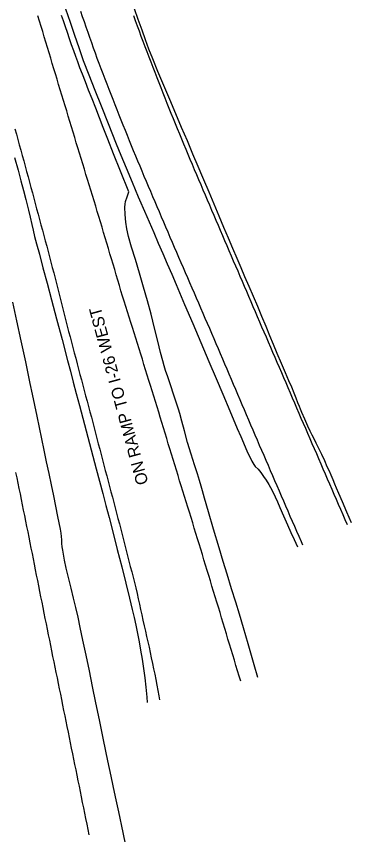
# Model space of a CAD drawing. Extents: x 1948091 to 1975253, y 787267 to 823306.
# Drawn here: x 1966562.1 to 1966713.8, y 789832.7 to 790203 of the extents above; entities that cross this region are included whole.
import ezdxf

# ---------------------------------------------------------------- set-up
doc = ezdxf.new("R2010")
doc.units = 0
for name, color, linetype in [('RD_EX_Pavement_Markings', 7, 'Continuous'), ('RD_EX_Road', 7, 'Continuous'), ('RD_TX_RoadID', 7, 'Continuous')]:
    doc.layers.add(name, color=color, linetype=linetype)

msp = doc.modelspace()

# ---------------------------------------------------------------- linework, layer by layer
at = {"layer": 'RD_EX_Pavement_Markings'}
for points in [[(1966591.11, 790205.32), (1966591.91, 790202.95), (1966592.71, 790200.59), (1966593.53, 790198.23), (1966594.37, 790195.87), (1966595.2, 790193.51), (1966596.03, 790191.16), (1966596.87, 790188.8), (1966597.7, 790186.45), (1966598.57, 790184.1), (1966599.45, 790181.76), (1966600.33, 790179.43), (1966601.21, 790177.09), (1966602.09, 790174.75), (1966602.97, 790172.41), (1966603.88, 790170.08), (1966604.8, 790167.76), (1966605.72, 790165.44), (1966606.64, 790163.11), (1966607.56, 790160.79), (1966608.48, 790158.47), (1966609.4, 790156.14), (1966610.34, 790153.83), (1966611.27, 790151.51), (1966612.21, 790149.2), (1966613.15, 790146.88), (1966614.08, 790144.56), (1966615.02, 790142.25), (1966615.97, 790139.94), (1966616.93, 790137.63), (1966617.9, 790135.33), (1966618.86, 790133.02), (1966619.82, 790130.71), (1966620.79, 790128.41), (1966621.75, 790126.1), (1966622.73, 790123.8), (1966623.71, 790121.51), (1966624.7, 790119.21), (1966625.68, 790116.91), (1966626.66, 790114.62), (1966627.65, 790112.32), (1966628.63, 790110.02), (1966629.62, 790107.73), (1966630.6, 790105.43), (1966631.59, 790103.13), (1966632.58, 790100.84), (1966633.56, 790098.54), (1966634.55, 790096.24), (1966635.54, 790093.95), (1966636.52, 790091.65), (1966637.52, 790089.36), (1966638.51, 790087.07), (1966639.51, 790084.78), (1966640.51, 790082.48), (1966641.5, 790080.19), (1966642.5, 790077.9), (1966643.5, 790075.61), (1966644.49, 790073.32), (1966645.48, 790071.02), (1966646.47, 790068.72), (1966647.46, 790066.43), (1966648.45, 790064.13), (1966649.44, 790061.84), (1966650.43, 790059.54), (1966651.42, 790057.25), (1966652.41, 790054.95), (1966653.39, 790052.65), (1966654.37, 790050.35), (1966655.35, 790048.06), (1966656.34, 790045.76), (1966657.32, 790043.46), (1966658.3, 790041.16), (1966659.28, 790038.86), (1966660.27, 790036.56), (1966661.24, 790034.26), (1966662.22, 790031.96), (1966663.2, 790029.66), (1966664.18, 790027.36), (1966665.15, 790025.06), (1966666.13, 790022.76), (1966667.11, 790020.46), (1966668.09, 790018.16), (1966669.08, 790015.86), (1966670.07, 790013.57), (1966671.07, 790011.28), (1966672.06, 790008.98), (1966673.06, 790006.69), (1966674.05, 790004.4), (1966675.05, 790002.1), (1966676.04, 789999.81), (1966677.04, 789997.52), (1966678.02, 789995.22), (1966679, 789992.92), (1966679.99, 789990.62), (1966680.97, 789988.32), (1966681.95, 789986.02), (1966682.94, 789983.73), (1966683.92, 789981.43), (1966684.9, 789979.13), (1966685.91, 789976.84), (1966686.91, 789974.55), (1966687.92, 789972.26), (1966688.92, 789969.97), (1966689.93, 789967.68), (1966690.93, 789965.39), (1966691.6, 789963.88)], [(1966663.63, 789902.06), (1966662.91, 789904.45), (1966662.19, 789906.84), (1966661.47, 789909.23), (1966660.75, 789911.63), (1966660.03, 789914.02), (1966659.31, 789916.41), (1966658.58, 789918.8), (1966657.86, 789921.19), (1966657.14, 789923.58), (1966656.42, 789925.97), (1966655.7, 789928.36), (1966654.98, 789930.75), (1966654.26, 789933.15), (1966653.54, 789935.54), (1966652.81, 789937.93), (1966652.09, 789940.32), (1966651.36, 789942.7), (1966650.63, 789945.09), (1966649.91, 789947.48), (1966649.18, 789949.87), (1966648.45, 789952.26), (1966647.73, 789954.65), (1966647, 789957.04), (1966646.27, 789959.43), (1966645.54, 789961.82), (1966644.82, 789964.21), (1966644.09, 789966.6), (1966643.36, 789968.99), (1966642.63, 789971.37), (1966641.89, 789973.76), (1966641.15, 789976.15), (1966640.42, 789978.53), (1966639.68, 789980.92), (1966638.94, 789983.31), (1966638.21, 789985.69), (1966637.47, 789988.08), (1966636.73, 789990.47), (1966635.99, 789992.85), (1966635.26, 789995.24), (1966634.52, 789997.63), (1966633.78, 790000.02), (1966633.05, 790002.4), (1966632.32, 790004.8), (1966631.6, 790007.19), (1966630.87, 790009.58), (1966630.15, 790011.97), (1966629.42, 790014.36), (1966628.69, 790016.75), (1966627.97, 790019.14), (1966627.24, 790021.53), (1966626.51, 790023.92), (1966625.77, 790026.31), (1966625.03, 790028.7), (1966624.29, 790031.08), (1966623.55, 790033.47), (1966622.81, 790035.85), (1966622.07, 790038.24), (1966621.33, 790040.63), (1966620.59, 790043.01), (1966619.85, 790045.4), (1966619.11, 790047.79), (1966618.36, 790050.17), (1966617.62, 790052.56), (1966616.87, 790054.94), (1966616.13, 790057.33), (1966615.38, 790059.72), (1966614.63, 790062.1), (1966613.89, 790064.48), (1966613.14, 790066.87), (1966612.4, 790069.26), (1966611.65, 790071.64), (1966610.9, 790074.03), (1966610.16, 790076.41), (1966609.42, 790078.8), (1966608.72, 790081.2), (1966608.02, 790083.6), (1966607.31, 790086), (1966606.61, 790088.4), (1966605.89, 790090.79), (1966605.17, 790093.19), (1966604.45, 790095.58), (1966603.74, 790097.98), (1966603.02, 790100.37), (1966602.3, 790102.77), (1966601.58, 790105.16), (1966600.86, 790107.55), (1966600.14, 790109.95), (1966599.43, 790112.34), (1966598.71, 790114.74), (1966597.99, 790117.13), (1966597.26, 790119.52), (1966596.53, 790121.91), (1966595.8, 790124.3), (1966595.07, 790126.7), (1966594.34, 790129.09), (1966593.6, 790131.48), (1966592.87, 790133.87), (1966592.14, 790136.26), (1966591.41, 790138.65), (1966590.68, 790141.04), (1966589.95, 790143.43), (1966589.22, 790145.82), (1966588.5, 790148.22), (1966587.77, 790150.61), (1966587.04, 790153), (1966586.31, 790155.39), (1966585.58, 790157.78), (1966584.86, 790160.17), (1966584.13, 790162.56), (1966583.4, 790164.96), (1966582.67, 790167.35), (1966581.94, 790169.74), (1966581.21, 790172.13), (1966580.49, 790174.52), (1966579.77, 790176.92), (1966579.05, 790179.31), (1966578.33, 790181.71), (1966577.61, 790184.1), (1966576.88, 790186.49), (1966576.16, 790188.89), (1966575.44, 790191.28), (1966574.72, 790193.67), (1966574, 790196.07), (1966573.28, 790198.46), (1966572.56, 790200.85), (1966571.84, 790203.25)], [(1966711.93, 789972.85), (1966710.93, 789975.15), (1966709.94, 789977.44), (1966708.94, 789979.74), (1966707.95, 789982.03), (1966706.96, 789984.32), (1966705.96, 789986.62), (1966704.97, 789988.91), (1966703.97, 789991.2), (1966702.98, 789993.5), (1966701.99, 789995.79), (1966701, 789998.09), (1966700.01, 790000.38), (1966699.02, 790002.68), (1966698.03, 790004.98), (1966697.04, 790007.27), (1966696.05, 790009.57), (1966695.05, 790011.86), (1966694.05, 790014.15), (1966693.06, 790016.44), (1966692.06, 790018.74), (1966691.07, 790021.03), (1966690.07, 790023.32), (1966689.07, 790025.62), (1966688.08, 790027.91), (1966687.1, 790030.21), (1966686.11, 790032.51), (1966685.13, 790034.81), (1966684.15, 790037.1), (1966683.16, 790039.4), (1966682.18, 790041.7), (1966681.19, 790044), (1966680.21, 790046.3), (1966679.21, 790048.59), (1966678.22, 790050.88), (1966677.23, 790053.18), (1966676.24, 790055.47), (1966675.25, 790057.77), (1966674.26, 790060.06), (1966673.26, 790062.36), (1966672.28, 790064.65), (1966671.29, 790066.95), (1966670.3, 790069.25), (1966669.31, 790071.54), (1966668.33, 790073.84), (1966667.34, 790076.14), (1966666.35, 790078.44), (1966665.37, 790080.73), (1966664.38, 790083.03), (1966663.4, 790085.33), (1966662.41, 790087.62), (1966661.42, 790089.92), (1966660.44, 790092.22), (1966659.45, 790094.51), (1966658.47, 790096.81), (1966657.48, 790099.11), (1966656.49, 790101.4), (1966655.51, 790103.7), (1966654.52, 790106), (1966653.54, 790108.29), (1966652.55, 790110.59), (1966651.56, 790112.89), (1966650.58, 790115.18), (1966649.59, 790117.48), (1966648.6, 790119.78), (1966647.62, 790122.07), (1966646.64, 790124.37), (1966645.67, 790126.68), (1966644.7, 790128.98), (1966643.73, 790131.28), (1966642.76, 790133.59), (1966641.79, 790135.89), (1966640.82, 790138.19), (1966639.85, 790140.5), (1966638.88, 790142.8), (1966637.93, 790145.11), (1966636.97, 790147.42), (1966636.02, 790149.73), (1966635.06, 790152.04), (1966634.1, 790154.35), (1966633.15, 790156.65), (1966632.19, 790158.96), (1966631.23, 790161.27), (1966630.31, 790163.59), (1966629.4, 790165.92), (1966628.49, 790168.25), (1966627.58, 790170.57), (1966626.67, 790172.9), (1966625.76, 790175.23), (1966624.85, 790177.56), (1966623.95, 790179.89), (1966623.06, 790182.23), (1966622.18, 790184.56), (1966621.29, 790186.9), (1966620.4, 790189.23), (1966619.51, 790191.57), (1966618.63, 790193.9), (1966617.77, 790196.25), (1966616.92, 790198.6), (1966616.07, 790200.95), (1966615.23, 790203.3)], [(1966561.43, 790152.13), (1966562.1, 790149.72), (1966562.76, 790147.31), (1966563.42, 790144.9), (1966564.09, 790142.49), (1966564.74, 790140.07), (1966565.39, 790137.66), (1966566.05, 790135.25), (1966566.7, 790132.84), (1966567.35, 790130.42), (1966568.01, 790128.01), (1966568.66, 790125.6), (1966569.31, 790123.18), (1966569.97, 790120.77), (1966570.62, 790118.36), (1966571.27, 790115.94), (1966571.92, 790113.53), (1966572.57, 790111.12), (1966573.22, 790108.7), (1966573.86, 790106.29), (1966574.51, 790103.87), (1966575.16, 790101.46), (1966575.8, 790099.04), (1966576.43, 790096.62), (1966577.07, 790094.21), (1966577.71, 790091.79), (1966578.35, 790089.37), (1966578.98, 790086.95), (1966579.62, 790084.54), (1966580.25, 790082.12), (1966580.86, 790079.69), (1966581.46, 790077.27), (1966582.07, 790074.84), (1966582.68, 790072.42), (1966583.29, 790069.99), (1966583.89, 790067.57), (1966584.5, 790065.14), (1966585.12, 790062.72), (1966585.75, 790060.3), (1966586.39, 790057.89), (1966587.03, 790055.47), (1966587.67, 790053.05), (1966588.3, 790050.64), (1966588.94, 790048.22), (1966589.58, 790045.8), (1966590.21, 790043.39), (1966590.86, 790040.97), (1966591.5, 790038.56), (1966592.15, 790036.14), (1966592.79, 790033.73), (1966593.44, 790031.31), (1966594.08, 790028.9), (1966594.73, 790026.48), (1966595.37, 790024.07), (1966596.02, 790021.66), (1966596.65, 790019.24), (1966597.28, 790016.82), (1966597.91, 790014.4), (1966598.54, 790011.98), (1966599.17, 790009.57), (1966599.8, 790007.15), (1966600.43, 790004.73), (1966601.06, 790002.31), (1966601.7, 789999.89), (1966602.33, 789997.48), (1966602.97, 789995.06), (1966603.61, 789992.65), (1966604.25, 789990.23), (1966604.89, 789987.81), (1966605.53, 789985.4), (1966606.16, 789982.98), (1966606.8, 789980.57), (1966607.44, 789978.15), (1966608.08, 789975.74), (1966608.7, 789973.32), (1966609.32, 789970.9), (1966609.94, 789968.48), (1966610.56, 789966.06), (1966611.18, 789963.64), (1966611.8, 789961.22), (1966612.42, 789958.8), (1966613.04, 789956.38), (1966613.66, 789953.96), (1966614.28, 789951.54), (1966614.91, 789949.13), (1966615.53, 789946.71), (1966616.16, 789944.29), (1966616.72, 789941.86), (1966617.28, 789939.43), (1966617.81, 789936.99), (1966618.34, 789934.55), (1966618.87, 789932.11), (1966619.4, 789929.67), (1966619.95, 789927.23), (1966620.49, 789924.79), (1966621.03, 789922.36), (1966621.58, 789919.92), (1966622.12, 789917.48), (1966622.64, 789915.04), (1966623.17, 789912.6), (1966623.7, 789910.16), (1966624.22, 789907.72), (1966624.75, 789905.28), (1966625.2, 789902.82), (1966625.65, 789900.37), (1966626.1, 789897.91), (1966626.53, 789895.45), (1966626.84, 789893.7)], [(1966561.76, 789996.62), (1966562.25, 789994.17), (1966562.75, 789991.73), (1966563.24, 789989.28), (1966563.74, 789986.83), (1966564.23, 789984.38), (1966564.73, 789981.93), (1966565.22, 789979.48), (1966565.72, 789977.03), (1966566.21, 789974.58), (1966566.7, 789972.14), (1966567.2, 789969.69), (1966567.69, 789967.24), (1966568.19, 789964.79), (1966568.68, 789962.34), (1966569.17, 789959.89), (1966569.66, 789957.44), (1966570.15, 789954.99), (1966570.63, 789952.54), (1966571.12, 789950.09), (1966571.61, 789947.64), (1966572.1, 789945.19), (1966572.59, 789942.74), (1966573.08, 789940.29), (1966573.57, 789937.84), (1966574.06, 789935.39), (1966574.55, 789932.94), (1966575.04, 789930.49), (1966575.53, 789928.04), (1966576.02, 789925.59), (1966576.52, 789923.14), (1966577.02, 789920.7), (1966577.51, 789918.25), (1966578.01, 789915.8), (1966578.51, 789913.35), (1966579, 789910.9), (1966579.5, 789908.45), (1966580, 789906.01), (1966580.49, 789903.56), (1966580.99, 789901.11), (1966581.49, 789898.66), (1966581.99, 789896.21), (1966582.48, 789893.77), (1966582.98, 789891.32), (1966583.48, 789888.87), (1966583.97, 789886.42), (1966584.47, 789883.97), (1966584.97, 789881.53), (1966585.47, 789879.08), (1966585.96, 789876.63), (1966586.46, 789874.18), (1966586.96, 789871.73), (1966587.45, 789869.29), (1966587.95, 789866.84), (1966588.45, 789864.39), (1966588.94, 789861.94), (1966589.44, 789859.5), (1966589.94, 789857.05), (1966590.44, 789854.6), (1966590.93, 789852.15), (1966591.43, 789849.7), (1966591.93, 789847.26), (1966592.42, 789844.81), (1966592.92, 789842.36), (1966593.42, 789839.91), (1966593.92, 789837.46), (1966594.43, 789835.02), (1966594.94, 789832.58)]]:
    msp.add_lwpolyline(points, dxfattribs=at)
at = {"layer": 'RD_EX_Road'}
for points in [[(1966584.38, 790206.41), (1966586.41, 790200.38), (1966588.43, 790194.43), (1966590.33, 790188.83), (1966592.39, 790183.06), (1966594.85, 790176.59), (1966597.58, 790169.64), (1966600.41, 790162.43), (1966603.57, 790154.48), (1966607.25, 790145.3), (1966609.36, 790140.13), (1966611.73, 790134.41), (1966614.43, 790127.98), (1966617.26, 790121.34), (1966617.87, 790119.92), (1966620.03, 790114.88), (1966622.16, 790109.95), (1966624.24, 790105.14), (1966626.3, 790100.39), (1966628.35, 790095.66), (1966630.39, 790090.94), (1966632.42, 790086.24), (1966634.41, 790081.59), (1966638.26, 790072.6), (1966641.92, 790063.96), (1966645.58, 790055.34), (1966649.23, 790046.79), (1966652.51, 790039.05), (1966655.47, 790032.03), (1966658.67, 790024.49), (1966662.09, 790016.46), (1966663.66, 790012.78), (1966666.43, 790006.31), (1966668.64, 790001.62), (1966669.51, 790000.17), (1966670.22, 789999.31), (1966671.49, 789998.05), (1966672.77, 789996.49), (1966674, 789994.8), (1966675.16, 789993.15), (1966676.38, 789991.14), (1966677.82, 789988.39), (1966679.2, 789985.57), (1966680.25, 789983.32), (1966681.39, 789980.76), (1966683.01, 789976.99), (1966684.77, 789972.92), (1966686.3, 789969.46), (1966687.76, 789966.23), (1966689.3, 789962.87)], [(1966646.47, 790130.1), (1966644.37, 790135.02), (1966642.01, 790140.6), (1966639.48, 790146.58), (1966636.89, 790152.68), (1966634.24, 790158.92), (1966631.54, 790165.29), (1966628.85, 790171.68), (1966626.19, 790178.01), (1966623.86, 790183.7), (1966622.11, 790188.19), (1966620.6, 790192.29), (1966618.96, 790196.8), (1966617.27, 790201.56), (1966615.59, 790206.4)], [(1966671.4, 789903.83), (1966669.74, 789909.52), (1966666.97, 789919.03), (1966664.87, 789926.25), (1966663.04, 789932.4), (1966661.37, 789937.88), (1966659.53, 789943.86), (1966657.45, 789950.59), (1966655.74, 789956.21), (1966653.84, 789962.52), (1966651.33, 789970.94), (1966649, 789978.75), (1966647.2, 789984.87), (1966646.27, 789988.23), (1966645.71, 789990.37), (1966645.01, 789992.87), (1966644.05, 789996), (1966642.75, 790000.05), (1966641.23, 790004.82), (1966639.62, 790010.13), (1966638.12, 790015.35), (1966636.94, 790019.83), (1966636.07, 790023.24), (1966635.49, 790025.26), (1966634.75, 790027.5), (1966633.4, 790031.61), (1966631.86, 790036.21), (1966630.59, 790039.92), (1966629.62, 790042.77), (1966628.96, 790044.77), (1966628.31, 790047.09), (1966627.33, 790050.93), (1966626.09, 790055.97), (1966624.67, 790061.88), (1966623.1, 790068.14), (1966621.45, 790074.26), (1966619.69, 790080.4), (1966617.84, 790086.71), (1966615.98, 790092.88), (1966614.23, 790098.57), (1966612.83, 790103.35), (1966612.05, 790106.79), (1966611.61, 790109.81), (1966611.28, 790113.35), (1966611.2, 790116.7), (1966611.32, 790118.04), (1966611.54, 790119.17), (1966612.18, 790121.28), (1966612.99, 790123.54), (1966609.24, 790132.87), (1966606.06, 790140.83), (1966603.45, 790147.42), (1966601.41, 790152.65), (1966599.69, 790157.12), (1966598.01, 790161.44), (1966596.37, 790165.61), (1966594.79, 790169.63), (1966593.31, 790173.38), (1966591.99, 790176.75), (1966590.84, 790179.74), (1966589.86, 790182.34), (1966588.95, 790184.8), (1966588.03, 790187.37), (1966587.09, 790190.05), (1966586.13, 790192.83), (1966585.18, 790195.61), (1966584.27, 790198.31), (1966583.39, 790200.92), (1966582.55, 790203.45)], [(1966561.2, 790139.09), (1966562.85, 790133.43), (1966564.17, 790128.57), (1966565.32, 790124.18), (1966566.35, 790120.14), (1966567.57, 790115.2), (1966568.32, 790112.05), (1966569.09, 790108.75), (1966569.68, 790106.15), (1966570.36, 790103.35), (1966571.23, 790100.05), (1966572.48, 790095.34), (1966574.13, 790089.17), (1966575.97, 790082.25), (1966577.98, 790074.66), (1966580.25, 790066.14), (1966582.74, 790056.76), (1966585.27, 790047.2), (1966586.54, 790042.4), (1966587.84, 790037.46), (1966589.22, 790032.28), (1966590.66, 790026.86), (1966592.17, 790021.19), (1966593.71, 790015.42), (1966595.24, 790009.68), (1966596.75, 790003.96), (1966598.25, 789998.28), (1966599.73, 789992.64), (1966601.19, 789987.06), (1966602.63, 789981.55), (1966604.05, 789976.11), (1966605.41, 789970.89), (1966607.78, 789961.67), (1966609.76, 789953.89), (1966611.59, 789946.54), (1966613.28, 789939.65), (1966614.54, 789934.48), (1966615.38, 789930.96), (1966616.16, 789927.42), (1966616.94, 789923.65), (1966617.65, 789919.9), (1966618.31, 789916.16), (1966618.96, 789912.12), (1966619.6, 789907.79), (1966620.18, 789903.56), (1966620.68, 789899.43), (1966621.14, 789894.9), (1966621.36, 789892.46)], [(1966713.85, 789973.7), (1966711.73, 789978.55), (1966709.69, 789983.23), (1966708.02, 789987.09), (1966707.02, 789989.47), (1966706.29, 789991.25), (1966705.44, 789993.3), (1966704.57, 789995.35), (1966703.75, 789997.16), (1966702.84, 789999.16), (1966701.67, 790001.79), (1966700.38, 790004.68), (1966699.07, 790007.45), (1966697.86, 790009.88), (1966696.85, 790011.78), (1966695.95, 790013.45), (1966695.07, 790015.2), (1966694.02, 790017.46), (1966692.61, 790020.66), (1966691.33, 790023.64), (1966690.67, 790025.27), (1966690.21, 790026.45), (1966689.56, 790028.09), (1966688.75, 790030.13), (1966687.82, 790032.46), (1966686.72, 790035.11), (1966685.42, 790038.08), (1966683.88, 790041.61), (1966682.05, 790045.95), (1966680.18, 790050.45), (1966678.51, 790054.46), (1966676.88, 790058.39), (1966675.13, 790062.63), (1966673.27, 790067.08), (1966671.36, 790071.64), (1966669.41, 790076.22), (1966667.45, 790080.72), (1966665.55, 790085.09), (1966663.78, 790089.23), (1966662, 790093.41), (1966660.12, 790097.87), (1966658.12, 790102.57), (1966656.03, 790107.5), (1966653.85, 790112.63), (1966651.62, 790117.95), (1966649.31, 790123.42), (1966646.93, 790129.03), (1966646.47, 790130.1)], [(1966611.65, 789827.79), (1966610.41, 789833.61), (1966608.4, 789843.04), (1966606.94, 789849.72), (1966605.84, 789854.8), (1966604.93, 789859.06), (1966603.5, 789866), (1966601.54, 789875.63), (1966599.71, 789884.55), (1966598.11, 789892.3), (1966596.61, 789899.67), (1966595.18, 789906.8), (1966593.71, 789913.82), (1966592.23, 789920.61), (1966590.99, 789926.38), (1966589.99, 789931.11), (1966589, 789935.46), (1966587.99, 789939.64), (1966586.87, 789944.16), (1966585.68, 789948.97), (1966584.67, 789953.29), (1966583.9, 789956.94), (1966583.38, 789959.6), (1966583.09, 789961.34), (1966582.88, 789962.93), (1966582.72, 789964.49), (1966582.61, 789966.03), (1966582.51, 789967.56), (1966582.35, 789969.03), (1966582, 789970.97), (1966580.88, 789976.59), (1966578.97, 789985.94), (1966577.94, 789991), (1966576.87, 789996.14), (1966575.78, 790001.38), (1966574.69, 790006.64), (1966573.6, 790011.82), (1966572.52, 790016.94), (1966571.45, 790021.99), (1966570.4, 790026.99), (1966569.36, 790031.95), (1966568.33, 790036.88), (1966566.32, 790046.62), (1966564.29, 790056.1), (1966562.27, 790065.25), (1966560.49, 790073.64)]]:
    msp.add_lwpolyline(points, dxfattribs=at)

# ---------------------------------------------------------------- texts
at = {"layer": 'RD_TX_RoadID'}
msp.add_text('ON RAMP TO I-26 WEST', height=5.4, rotation=105.1842, dxfattribs=at).set_placement((1966621.88, 789991.76))

doc.saveas('drawing.dxf')
